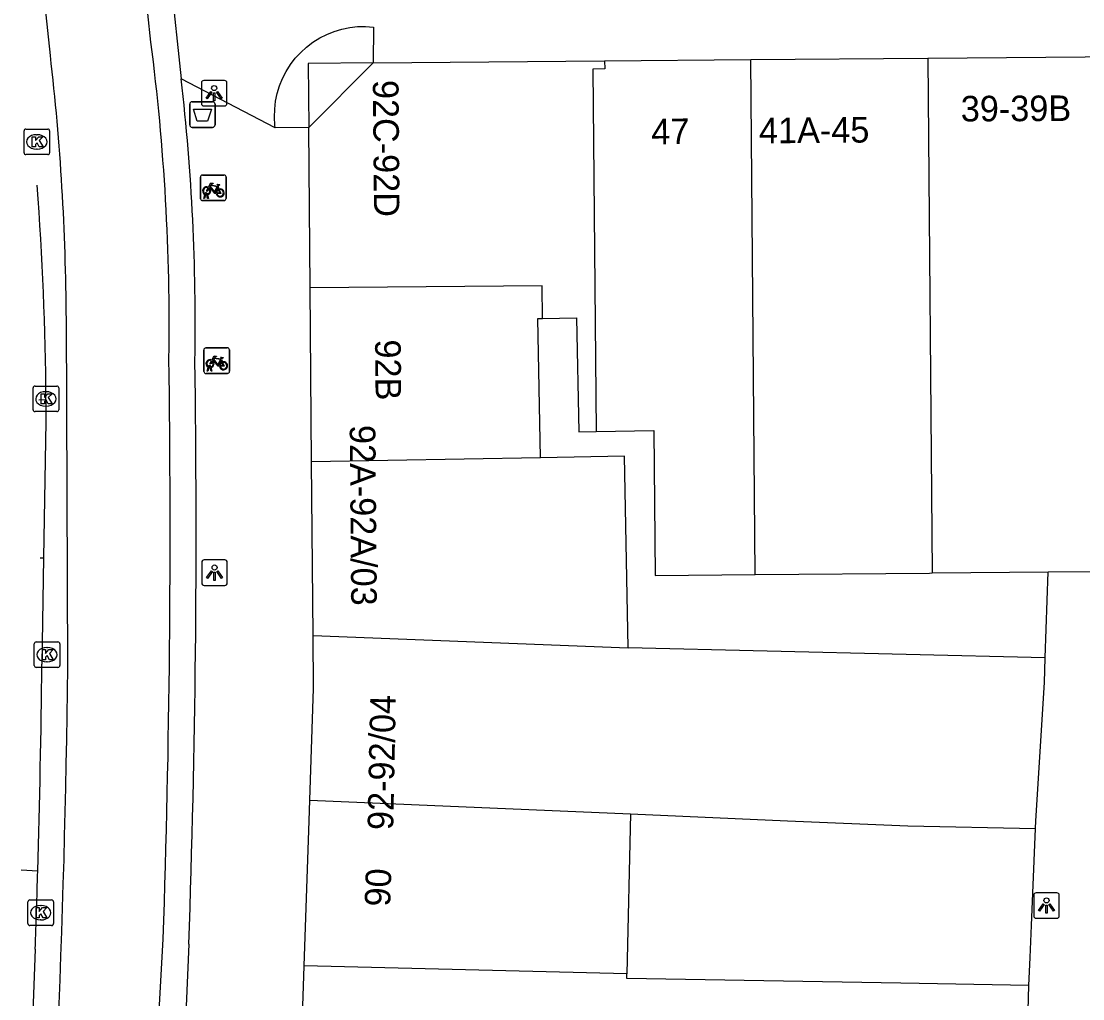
# Model space of a CAD drawing. Extents: x 160861 to 161308, y 384024 to 384878.
# Drawn here: x 161130.02 to 161171.49, y 384243.04 to 384281.25 of the extents above; entities that cross this region are included whole.
import ezdxf

# ---------------------------------------------------------------- set-up
doc = ezdxf.new("R2010")
doc.units = 0
for name, color, linetype in [('IMGEO_Afvalbak', 7, 'Continuous'), ('IMGEO_Fietsenrek', 7, 'Continuous'), ('IMGEO_Fietspad_gesloten', 7, 'Continuous'), ('IMGEO_Fietspad_open', 7, 'Continuous'), ('IMGEO_Kolk', 7, 'Continuous'), ('IMGEO_Lichtpunt', 7, 'Continuous'), ('IMGEO_Pand', 7, 'Continuous'), ('IMGEO_Pand_nummerreeks', 7, 'Continuous'), ('IMGEO_Pand_overbouw', 7, 'Continuous'), ('IMGEO_Rijbaan_lokaal_open', 7, 'Continuous'), ('IMGEO_Voetpad_open', 7, 'Continuous')]:
    doc.layers.add(name, color=color, linetype=linetype)

msp = doc.modelspace()

# ---------------------------------------------------------------- linework, layer by layer
at = {"layer": 'IMGEO_Afvalbak'}
for p, q in [((161136.604, 384277.202), (161136.604, 384278.002)), ((161136.604, 384278.002), (161136.604, 384277.202)), ((161136.704, 384278.102), (161137.494, 384278.102)), ((161137.494, 384278.102), (161136.704, 384278.102)), ((161137.594, 384278.002), (161137.594, 384277.202)), ((161137.594, 384277.202), (161137.594, 384278.002)), ((161137.494, 384277.102), (161136.704, 384277.102)), ((161136.704, 384277.102), (161137.494, 384277.102))]:
    msp.add_line(p, q, dxfattribs=at)
msp.add_lwpolyline([(161136.747, 384277.816), (161137.451, 384277.816), (161137.302, 384277.346), (161136.896, 384277.346), (161136.747, 384277.816)], dxfattribs=at)
for centre, start, end in [((161136.704, 384278.002), 90, 180), ((161136.704, 384278.002), 90, 180), ((161137.494, 384278.002), 0, 90), ((161137.494, 384278.002), 360, 90), ((161136.704, 384277.202), 180, 270), ((161136.704, 384277.202), 180, 270), ((161137.494, 384277.202), 270, 0), ((161137.494, 384277.202), 270, 0)]:
    msp.add_arc(centre, 0.1, start, end, dxfattribs=at)
at = {"layer": 'IMGEO_Fietsenrek'}
for p, q in [((161137.026, 384274.313), (161137.026, 384275.154)), ((161137.026, 384275.154), (161137.026, 384274.313)), ((161137.101, 384275.238), (161137.942, 384275.238)), ((161137.942, 384275.238), (161137.101, 384275.238)), ((161138.026, 384275.163), (161138.026, 384274.322)), ((161138.026, 384274.322), (161138.026, 384275.163)), ((161137.153, 384274.322), (161137.192, 384274.482)), ((161137.222, 384274.47), (161137.187, 384274.322)), ((161137.264, 384274.494), (161137.263, 384274.498)), ((161137.305, 384274.322), (161137.271, 384274.464)), ((161137.295, 384274.505), (161137.296, 384274.498)), ((161137.303, 384274.468), (161137.338, 384274.322)), ((161137.713, 384274.787), (161137.749, 384274.692)), ((161137.951, 384274.238), (161137.11, 384274.238)), ((161137.11, 384274.238), (161137.951, 384274.238)), ((161137.187, 384274.322), (161137.153, 384274.322)), ((161137.338, 384274.322), (161137.305, 384274.322)), ((161137.158, 384267.557), (161137.158, 384268.398)), ((161137.158, 384268.398), (161137.158, 384267.557)), ((161137.233, 384268.482), (161138.074, 384268.482)), ((161138.074, 384268.482), (161137.233, 384268.482)), ((161138.158, 384268.407), (161138.158, 384267.566)), ((161138.158, 384267.566), (161138.158, 384268.407)), ((161137.845, 384268.031), (161137.881, 384267.936)), ((161138.083, 384267.482), (161137.242, 384267.482)), ((161137.242, 384267.482), (161138.083, 384267.482)), ((161137.285, 384267.566), (161137.324, 384267.726)), ((161137.319, 384267.566), (161137.285, 384267.566)), ((161137.354, 384267.714), (161137.319, 384267.566)), ((161137.396, 384267.738), (161137.395, 384267.742)), ((161137.437, 384267.566), (161137.403, 384267.708)), ((161137.427, 384267.749), (161137.428, 384267.742)), ((161137.435, 384267.712), (161137.47, 384267.566)), ((161137.47, 384267.566), (161137.437, 384267.566))]:
    msp.add_line(p, q, dxfattribs=at)
for points in [[(161137.339, 384274.764), (161137.434, 384274.928), (161137.52, 384274.914), (161137.522, 384274.905), (161137.466, 384274.894), (161137.439, 384274.849), (161137.695, 384274.808)], [(161137.695, 384274.808), (161137.72, 384274.857), (161137.714, 384274.861), (161137.691, 384274.865), (161137.679, 384274.872), (161137.678, 384274.875), (161137.68, 384274.88), (161137.775, 384274.865), (161137.777, 384274.855), (161137.767, 384274.842), (161137.755, 384274.836), (161137.741, 384274.842), (161137.713, 384274.787)], [(161137.36, 384274.712), (161137.308, 384274.622), (161137.268, 384274.597), (161137.269, 384274.644), (161137.324, 384274.738)], [(161137.635, 384274.52), (161137.585, 384274.52), (161137.394, 384274.771), (161137.375, 384274.739)], [(161137.682, 384274.783), (161137.425, 384274.824), (161137.408, 384274.795), (161137.575, 384274.575), (161137.682, 384274.783)], [(161137.73, 384274.685), (161137.7, 384274.762), (161137.591, 384274.544), (161137.634, 384274.544)], [(161137.664, 384274.544), (161137.784, 384274.543), (161137.74, 384274.657)], [(161137.76, 384274.664), (161137.815, 384274.519), (161137.665, 384274.519)], [(161137.492, 384267.956), (161137.44, 384267.866), (161137.4, 384267.841), (161137.401, 384267.888), (161137.456, 384267.982)], [(161137.471, 384268.008), (161137.566, 384268.172), (161137.652, 384268.158), (161137.654, 384268.149), (161137.598, 384268.138), (161137.571, 384268.093), (161137.827, 384268.052)], [(161137.767, 384267.764), (161137.717, 384267.764), (161137.526, 384268.015), (161137.507, 384267.983)], [(161137.814, 384268.027), (161137.557, 384268.068), (161137.54, 384268.039), (161137.707, 384267.819), (161137.814, 384268.027)], [(161137.862, 384267.929), (161137.832, 384268.006), (161137.723, 384267.788), (161137.766, 384267.788)], [(161137.796, 384267.788), (161137.916, 384267.787), (161137.872, 384267.901)], [(161137.892, 384267.908), (161137.947, 384267.763), (161137.797, 384267.763)], [(161137.827, 384268.052), (161137.852, 384268.101), (161137.846, 384268.105), (161137.823, 384268.109), (161137.811, 384268.116), (161137.81, 384268.119), (161137.812, 384268.124), (161137.907, 384268.109), (161137.909, 384268.099), (161137.899, 384268.086), (161137.887, 384268.08), (161137.873, 384268.086), (161137.845, 384268.031)]]:
    msp.add_lwpolyline(points, dxfattribs=at)
for centre, radius, start, end in [((161137.104, 384275.16), 0.0779, 92.4484, 184.2845), ((161137.104, 384275.16), 0.0779, 92.4484, 184.2845), ((161137.948, 384275.16), 0.0779, 2.4484, 94.2845), ((161137.948, 384275.16), 0.0779, 2.4484, 94.2845), ((161137.266, 384274.623), 0.159, 62.6766, 242.1369), ((161137.266, 384274.623), 0.129, 63.3192, 238.903), ((161137.246, 384274.494), 0.0499, 12.8025, 158.6934), ((161137.266, 384274.623), 0.159, 253.9967, 271.7867), ((161137.246, 384274.494), 0.0174, 12.8025, 163.4502), ((161137.266, 384274.623), 0.129, 253.415, 269.0204), ((161137.266, 384274.623), 0.129, 283.6043, 43.4302), ((161137.266, 384274.623), 0.159, 283.5766, 46.6042), ((161137.793, 384274.539), 0.159, 113.3408, 178.3217), ((161137.793, 384274.539), 0.159, 187.0065, 105.7708), ((161137.793, 384274.539), 0.129, 113.923, 177.9556), ((161137.793, 384274.539), 0.129, 188.6715, 104.5883), ((161137.104, 384274.316), 0.0779, 182.4484, 274.2845), ((161137.104, 384274.316), 0.0779, 182.4484, 274.2845), ((161137.948, 384274.316), 0.0779, 272.4484, 4.2845), ((161137.948, 384274.316), 0.0779, 272.4484, 4.2845), ((161137.236, 384268.404), 0.0779, 92.4484, 184.2845), ((161137.236, 384268.404), 0.0779, 92.4484, 184.2845), ((161138.08, 384268.404), 0.0779, 2.4484, 94.2845), ((161138.08, 384268.404), 0.0779, 2.4484, 94.2845), ((161137.398, 384267.867), 0.159, 62.6766, 242.1369), ((161137.398, 384267.867), 0.129, 63.3192, 238.903), ((161137.398, 384267.867), 0.129, 283.6043, 43.4302), ((161137.398, 384267.867), 0.159, 283.5766, 46.6042), ((161137.925, 384267.783), 0.159, 113.3408, 178.3217), ((161137.925, 384267.783), 0.159, 187.0065, 105.7708), ((161137.925, 384267.783), 0.129, 113.923, 177.9556), ((161137.925, 384267.783), 0.129, 188.6715, 104.5883), ((161137.236, 384267.56), 0.0779, 182.4484, 274.2845), ((161137.236, 384267.56), 0.0779, 182.4484, 274.2845), ((161137.378, 384267.738), 0.0499, 12.8025, 158.6934), ((161137.398, 384267.867), 0.159, 253.9967, 271.7867), ((161137.378, 384267.738), 0.0174, 12.8025, 163.4502), ((161137.398, 384267.867), 0.129, 253.415, 269.0204), ((161138.08, 384267.56), 0.0779, 272.4484, 4.2845), ((161138.08, 384267.56), 0.0779, 272.4484, 4.2845)]:
    msp.add_arc(centre, radius, start, end, dxfattribs=at)
at = {"layer": 'IMGEO_Fietspad_gesloten'}
for points in [[(161135.089, 384280.432), (161134.613, 384284.922), (161133.548, 384294.958), (161132.338, 384304.153)], [(161131.163, 384279.913), (161130.552, 384285.673)], [(161131.844, 384255.987), (161131.786, 384269.584)], [(161134.478, 384225.642), (161135.573, 384245.386)]]:
    msp.add_lwpolyline(points, dxfattribs=at)
for centre, radius, start, end in [((161049.82, 384269.383), 85.982, 359.1311, 7.3832), ((161036.627, 384269.028), 95.16, 0.33492, 6.56837), ((160657.158, 384261.351), 478.681, 358.08877, 0.80539), ((160666.285, 384261.528), 465.592, 355.61967, 359.31806)]:
    msp.add_arc(centre, radius, start, end, dxfattribs=at)
at = {"layer": 'IMGEO_Fietspad_open'}
for points in [[(161135.868, 384282.811), (161136.27, 384278.993)], [(161130.99, 384266.451), (161130.99, 384266.406), (161130.978, 384265.608), (161130.894, 384260.276)], [(161130.894, 384260.276), (161130.829, 384256.122)], [(161136.568, 384245.17), (161136.252, 384237.908)], [(161130.568, 384244.986), (161130.472, 384242.522)]]:
    msp.add_lwpolyline(points, dxfattribs=at)
for centre, radius, start, end in [((161054.056, 384269.465), 82.764, 358.97397, 6.61068), ((161012.207, 384265.72), 118.785, 0.35278, 4.40188), ((160683.42, 384261.325), 453.436, 357.95822, 0.84131), ((160713.448, 384260.382), 417.403, 358.30454, 359.41527), ((160743.615, 384259.214), 387.215, 357.89418, 358.34514)]:
    msp.add_arc(centre, radius, start, end, dxfattribs=at)
at = {"layer": 'IMGEO_Kolk'}
for p, q in [((161130.132, 384276.109), (161130.132, 384276.961)), ((161130.207, 384277.035), (161131.059, 384277.035)), ((161131.133, 384276.961), (161131.133, 384276.109)), ((161130.62, 384276.815), (161130.645, 384276.815)), ((161130.643, 384276.255), (161130.618, 384276.255)), ((161131.059, 384276.035), (161130.207, 384276.035)), ((161130.562, 384266.99), (161131.414, 384266.99)), ((161130.487, 384266.064), (161130.487, 384266.916)), ((161130.975, 384266.77), (161131, 384266.77)), ((161131.488, 384266.916), (161131.488, 384266.064)), ((161130.998, 384266.21), (161130.973, 384266.21)), ((161131.414, 384265.99), (161130.562, 384265.99)), ((161130.53, 384256.065), (161130.53, 384256.917)), ((161130.605, 384256.991), (161131.457, 384256.991)), ((161131.018, 384256.771), (161131.043, 384256.771)), ((161131.531, 384256.917), (161131.531, 384256.065)), ((161131.041, 384256.211), (161131.016, 384256.211)), ((161131.457, 384255.991), (161130.605, 384255.991)), ((161130.283, 384245.978), (161130.283, 384246.83)), ((161130.358, 384246.904), (161131.21, 384246.904)), ((161130.771, 384246.684), (161130.796, 384246.684)), ((161131.284, 384246.83), (161131.284, 384245.978)), ((161131.21, 384245.904), (161130.358, 384245.904)), ((161130.794, 384246.124), (161130.769, 384246.124))]:
    msp.add_line(p, q, dxfattribs=at)
for points in [[(161130.132, 384276.109), (161130.132, 384276.961)], [(161130.207, 384277.035), (161131.059, 384277.035)], [(161131.133, 384276.961), (161131.133, 384276.109)], [(161130.453, 384276.735), (161130.576, 384276.735), (161130.576, 384276.584), (161130.706, 384276.735), (161130.87, 384276.735), (161130.724, 384276.584), (161130.877, 384276.335), (161130.725, 384276.335), (161130.64, 384276.499), (161130.576, 384276.432), (161130.576, 384276.335), (161130.453, 384276.335), (161130.453, 384276.735)], [(161131.059, 384276.035), (161130.207, 384276.035)], [(161130.562, 384266.99), (161131.414, 384266.99)], [(161130.487, 384266.064), (161130.487, 384266.916)], [(161130.808, 384266.69), (161130.931, 384266.69), (161130.931, 384266.539), (161131.061, 384266.69), (161131.225, 384266.69), (161131.079, 384266.539), (161131.232, 384266.29), (161131.08, 384266.29), (161130.995, 384266.454), (161130.931, 384266.387), (161130.931, 384266.29), (161130.808, 384266.29), (161130.808, 384266.69)], [(161131.488, 384266.916), (161131.488, 384266.064)], [(161131.414, 384265.99), (161130.562, 384265.99)], [(161130.53, 384256.065), (161130.53, 384256.917)], [(161130.605, 384256.991), (161131.457, 384256.991)], [(161130.851, 384256.691), (161130.974, 384256.691), (161130.974, 384256.54), (161131.104, 384256.691), (161131.268, 384256.691), (161131.122, 384256.54), (161131.275, 384256.291), (161131.123, 384256.291), (161131.038, 384256.455), (161130.974, 384256.388), (161130.974, 384256.291), (161130.851, 384256.291), (161130.851, 384256.691)], [(161131.531, 384256.917), (161131.531, 384256.065)], [(161131.457, 384255.991), (161130.605, 384255.991)], [(161130.283, 384245.978), (161130.283, 384246.83)], [(161130.358, 384246.904), (161131.21, 384246.904)], [(161131.284, 384246.83), (161131.284, 384245.978)], [(161130.604, 384246.604), (161130.727, 384246.604), (161130.727, 384246.453), (161130.857, 384246.604), (161131.021, 384246.604), (161130.875, 384246.453), (161131.028, 384246.204), (161130.876, 384246.204), (161130.791, 384246.368), (161130.727, 384246.301), (161130.727, 384246.204), (161130.604, 384246.204), (161130.604, 384246.604)], [(161131.21, 384245.904), (161130.358, 384245.904)]]:
    msp.add_lwpolyline(points, dxfattribs=at)
for centre, start, end in [((161130.209, 384276.959), 91.552, 178.448), ((161130.209, 384276.959), 91.552, 178.448), ((161131.057, 384276.959), 1.552, 88.448), ((161131.057, 384276.959), 1.552, 88.448), ((161130.209, 384276.111), 181.552, 268.448), ((161130.209, 384276.111), 181.552, 268.448), ((161131.057, 384276.111), 271.552, 358.448), ((161131.057, 384276.111), 271.552, 358.448), ((161130.564, 384266.914), 91.552, 178.448), ((161130.564, 384266.914), 91.552, 178.448), ((161131.412, 384266.914), 1.552, 88.448), ((161131.412, 384266.914), 1.552, 88.448), ((161130.564, 384266.066), 181.552, 268.448), ((161130.564, 384266.066), 181.552, 268.448), ((161131.412, 384266.066), 271.552, 358.448), ((161131.412, 384266.066), 271.552, 358.448), ((161130.607, 384256.915), 91.552, 178.448), ((161130.607, 384256.915), 91.552, 178.448), ((161131.455, 384256.915), 1.552, 88.448), ((161131.455, 384256.915), 1.552, 88.448), ((161130.607, 384256.067), 181.552, 268.448), ((161130.607, 384256.067), 181.552, 268.448), ((161131.455, 384256.067), 271.552, 358.448), ((161131.455, 384256.067), 271.552, 358.448), ((161130.36, 384246.828), 91.552, 178.448), ((161130.36, 384246.828), 91.552, 178.448), ((161131.208, 384246.828), 1.552, 88.448), ((161131.208, 384246.828), 1.552, 88.448), ((161130.36, 384245.98), 181.552, 268.448), ((161130.36, 384245.98), 181.552, 268.448), ((161131.208, 384245.98), 271.552, 358.448), ((161131.208, 384245.98), 271.552, 358.448)]:
    msp.add_arc(centre, 0.0765, start, end, dxfattribs=at)
for centre, major_axis, ratio, start_param, end_param in [((161130.619, 384276.535), (-0.387, 0.002), 0.722429, 4.712389, 7.853982), ((161130.644, 384276.535), (-0.39, 0.002), 0.717154, 1.570796, 4.712389), ((161130.974, 384266.49), (-0.387, 0.002), 0.722429, 4.712389, 7.853982), ((161130.999, 384266.49), (-0.39, 0.002), 0.717154, 1.570796, 4.712389), ((161131.017, 384256.491), (-0.387, 0.002), 0.722429, 4.712389, 7.853982), ((161131.042, 384256.491), (-0.39, 0.002), 0.717154, 1.570796, 4.712389), ((161130.77, 384246.404), (-0.387, 0.002), 0.722429, 4.712389, 7.853982), ((161130.795, 384246.404), (-0.39, 0.002), 0.717154, 1.570796, 4.712389)]:
    msp.add_ellipse(centre, major_axis=major_axis, ratio=ratio, start_param=start_param, end_param=end_param, dxfattribs=at)
at = {"layer": 'IMGEO_Lichtpunt'}
for p, q in [((161137.061, 384278.838), (161137.061, 384278.031)), ((161137.061, 384278.838), (161137.061, 384278.031)), ((161137.963, 384278.933), (161137.155, 384278.933)), ((161137.963, 384278.933), (161137.155, 384278.933)), ((161138.057, 384278.031), (161138.057, 384278.838)), ((161138.057, 384278.031), (161138.057, 384278.838)), ((161137.155, 384277.937), (161137.963, 384277.937)), ((161137.155, 384277.937), (161137.963, 384277.937)), ((161137.077, 384260.1), (161137.077, 384259.293)), ((161137.077, 384260.1), (161137.077, 384259.293)), ((161137.979, 384260.195), (161137.171, 384260.195)), ((161137.979, 384260.195), (161137.171, 384260.195)), ((161138.073, 384259.293), (161138.073, 384260.1)), ((161138.073, 384259.293), (161138.073, 384260.1)), ((161137.171, 384259.199), (161137.979, 384259.199)), ((161137.171, 384259.199), (161137.979, 384259.199)), ((161169.579, 384247.088), (161169.579, 384246.281)), ((161169.579, 384247.088), (161169.579, 384246.281)), ((161170.481, 384247.183), (161169.673, 384247.183)), ((161170.481, 384247.183), (161169.673, 384247.183)), ((161170.575, 384246.281), (161170.575, 384247.088)), ((161170.575, 384246.281), (161170.575, 384247.088)), ((161169.673, 384246.187), (161170.481, 384246.187)), ((161169.673, 384246.187), (161170.481, 384246.187))]:
    msp.add_line(p, q, dxfattribs=at)
for points in [[(161137.435, 384278.502), (161137.474, 384278.474), (161137.286, 384278.212), (161137.248, 384278.239), (161137.435, 384278.502)], [(161137.537, 384278.454), (161137.584, 384278.454), (161137.584, 384278.132), (161137.537, 384278.132), (161137.537, 384278.454)], [(161137.647, 384278.474), (161137.685, 384278.501), (161137.872, 384278.239), (161137.833, 384278.211), (161137.647, 384278.474)], [(161137.451, 384259.764), (161137.49, 384259.736), (161137.302, 384259.474), (161137.264, 384259.501), (161137.451, 384259.764)], [(161137.553, 384259.716), (161137.6, 384259.716), (161137.6, 384259.394), (161137.553, 384259.394), (161137.553, 384259.716)], [(161137.663, 384259.736), (161137.701, 384259.763), (161137.888, 384259.501), (161137.849, 384259.473), (161137.663, 384259.736)], [(161169.953, 384246.752), (161169.992, 384246.724), (161169.804, 384246.462), (161169.766, 384246.489), (161169.953, 384246.752)], [(161170.055, 384246.704), (161170.102, 384246.704), (161170.102, 384246.382), (161170.055, 384246.382), (161170.055, 384246.704)], [(161170.165, 384246.724), (161170.203, 384246.751), (161170.39, 384246.489), (161170.351, 384246.461), (161170.165, 384246.724)]]:
    msp.add_lwpolyline(points, dxfattribs=at)
for centre in [(161137.56, 384278.636), (161137.576, 384259.898), (161170.078, 384246.886)]:
    msp.add_circle(centre, 0.0994, dxfattribs=at)
for centre, start, end in [((161137.155, 384278.838), 90, 180), ((161137.155, 384278.838), 90, 180), ((161137.963, 384278.838), 0, 90), ((161137.963, 384278.838), 0, 90), ((161137.155, 384278.031), 180, 270), ((161137.155, 384278.031), 180, 270), ((161137.963, 384278.031), 270, 0), ((161137.963, 384278.031), 270, 360), ((161137.171, 384260.1), 90, 180), ((161137.171, 384260.1), 90, 180), ((161137.979, 384260.1), 0, 90), ((161137.979, 384260.1), 0, 90), ((161137.171, 384259.293), 180, 270), ((161137.171, 384259.293), 180, 270), ((161137.979, 384259.293), 270, 0), ((161137.979, 384259.293), 270, 360), ((161169.673, 384247.088), 90, 180), ((161169.673, 384247.088), 90, 180), ((161170.481, 384247.088), 0, 90), ((161170.481, 384247.088), 0, 90), ((161169.673, 384246.281), 180, 270), ((161169.673, 384246.281), 180, 270), ((161170.481, 384246.281), 270, 0), ((161170.481, 384246.281), 270, 360)]:
    msp.add_arc(centre, 0.0946, start, end, dxfattribs=at)
at = {"layer": 'IMGEO_Pand'}
for points in [[(161165.444, 384279.809), (161173.123, 384279.875)], [(161143.777, 384279.624), (161141.256, 384277.091)], [(161143.777, 384279.624), (161152.816, 384279.701)], [(161152.816, 384279.701), (161152.819, 384279.386), (161152.36, 384279.382), (161152.482, 384265.215)], [(161152.816, 384279.701), (161158.523, 384279.75)], [(161158.523, 384279.75), (161165.444, 384279.809)], [(161158.696, 384259.625), (161158.523, 384279.75)], [(161165.444, 384279.809), (161165.617, 384259.684)], [(161141.31, 384270.831), (161141.256, 384277.091)], [(161150.391, 384269.633), (161150.379, 384270.909), (161141.31, 384270.831)], [(161141.368, 384264.026), (161141.31, 384270.831)], [(161150.305, 384264.184), (161150.202, 384269.629), (161150.391, 384269.633)], [(161150.391, 384269.633), (161151.719, 384269.658), (161151.804, 384265.202), (161152.482, 384265.215)], [(161152.482, 384265.215), (161154.743, 384265.258), (161154.793, 384259.591), (161158.696, 384259.625)], [(161150.305, 384264.184), (161141.368, 384264.026)], [(161153.738, 384256.763), (161153.595, 384264.247), (161150.305, 384264.184)], [(161141.426, 384257.244), (161141.368, 384264.026)], [(161170.142, 384259.723), (161172.586, 384259.744), (161172.556, 384263.247)], [(161158.696, 384259.625), (161165.506, 384259.683), (161165.617, 384259.684)], [(161165.617, 384259.684), (161170.142, 384259.723)], [(161141.296, 384250.803), (161141.444, 384255.163), (161141.426, 384257.244)], [(161141.426, 384257.244), (161153.738, 384256.763)], [(161170.031, 384256.365), (161153.738, 384256.763)], [(161169.644, 384249.7), (161169.663, 384250), (161169.999, 384255.404), (161170.031, 384256.365)], [(161141.077, 384244.333), (161141.269, 384250), (161141.296, 384250.803)], [(161141.296, 384250.803), (161153.827, 384250.264)], [(161153.827, 384250.264), (161153.683, 384244.012)], [(161153.827, 384250.264), (161159.957, 384250), (161164.66, 384249.798), (161169.644, 384249.7)], [(161140.869, 384237.95), (161140.916, 384239.606), (161141.077, 384244.333)], [(161153.683, 384244.012), (161141.077, 384244.333)], [(161169.389, 384243.561), (161164.39, 384243.649), (161153.679, 384243.836), (161153.683, 384244.012)], [(161169.218, 384237.149), (161169.389, 384243.561)]]:
    msp.add_lwpolyline(points, dxfattribs=at)
at = {"layer": 'IMGEO_Pand_overbouw'}
msp.add_lwpolyline([(161141.256, 384277.091), (161143.777, 384279.624), (161141.234, 384279.602)], close=True, dxfattribs=at)
at = {"layer": 'IMGEO_Rijbaan_lokaal_open'}
for points in [[(161170.031, 384256.365), (161170.142, 384259.723)], [(161169.389, 384243.561), (161169.434, 384244.65), (161169.487, 384245.909), (161169.644, 384249.7)]]:
    msp.add_lwpolyline(points, dxfattribs=at)
at = {"layer": 'IMGEO_Voetpad_open'}
for points in [[(161139.948, 384277.078), (161139.934, 384277.189), (161139.915, 384277.5), (161139.924, 384277.812), (161139.96, 384278.121), (161140.024, 384278.426), (161140.115, 384278.725), (161140.232, 384279.013), (161140.375, 384279.29), (161140.542, 384279.554), (161140.731, 384279.801), (161140.942, 384280.031), (161141.173, 384280.24), (161141.421, 384280.429), (161141.685, 384280.594), (161141.963, 384280.735), (161142.253, 384280.851), (161142.551, 384280.94), (161142.857, 384281.002), (161143.166, 384281.037), (161143.478, 384281.044), (161143.789, 384281.023), (161143.777, 384279.624)], [(161139.948, 384277.078), (161136.27, 384278.993)], [(161141.256, 384277.091), (161139.948, 384277.078)], [(161130.99, 384266.451), (161130.711, 384266.443)], [(161130.762, 384260.277), (161130.894, 384260.276)], [(161130.668, 384248.032), (161130.023, 384248.063)]]:
    msp.add_lwpolyline(points, dxfattribs=at)

# ---------------------------------------------------------------- texts
at = {"layer": 'IMGEO_Pand_nummerreeks'}
for s, rotation, p in [('92C-92D', 270.4912, (161143.76, 384278.948)), ('39-39B', 0.2922, (161166.731, 384277.33)), ('47', 0.49, (161154.642, 384276.437)), ('41A-45', 0.4884, (161158.849, 384276.473)), ('92B', 270.4912, (161143.847, 384268.806)), ('92A-92A/03', 270.4925, (161142.855, 384265.465)), ('92-92/04', 88.8428, (161144.553, 384249.629)), ('90', 88.0522, (161144.436, 384246.634))]:
    msp.add_text(s, height=1, rotation=rotation, dxfattribs=at).set_placement(p)

doc.saveas('drawing.dxf')
